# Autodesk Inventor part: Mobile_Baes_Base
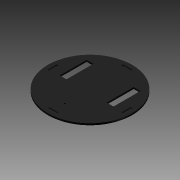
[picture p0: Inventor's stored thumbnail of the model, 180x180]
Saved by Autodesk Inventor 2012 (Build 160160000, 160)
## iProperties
Created: 2014-02
Part Number: Mobile_Baes_Base
Material: Default
Document SubType Name: Modeling
Designer: Aser
Density: 1 g/cm^3
Author: Aser
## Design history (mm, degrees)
sketch "Sketch1"
  geometry: C1 r 250 at (0, 0); 1 further point
  constraints: 1 centre point, 1 coincident
  dimensions: "d0" = 500 diameter of C1
extrude "Extrusion1" new body sketch "Sketch1" distance "d1" = 10; taper "d2" = 0 deg
sketch "Sketch2"
  geometry: L1 (-160, 140)-(-120, 140); L2 (-120, 140)-(-120, -20); L3 (-120, -20)-(-160, -20); L4 (-160, -20)-(-160, 140); L5 (120, 140)-(160, 140); L6 (160, 140)-(160, -20); L7 (160, -20)-(120, -20); L8 (120, -20)-(120, 140); L9 (0, 0)-(250, 0); L10 (0, 0)-(-250, 0); A1 r 250 centre (0, 0) between (250, 0) and (-250, 0) reference
  constraints: 20 end point, 5 equal length, 3 perpendicular, 2 horizontal, 2 point on circle
  dimensions: "d3" = 40 distance of L2.end L3.end; "d4" = 160 distance of L1.end L2.end; "d5" = 40 distance of L6.end L7.end; "d6" = 160 distance of L5.end L6.end; "d8" = 20 distance between parallel lines of L10 L3 (= d9); "d9" = 20 distance between parallel lines of L9 L7; "d10" = 120 distance from line of L9.start L8; "d11" = 120 distance from line of L9.start L2 (= d10)
extrude "Extrusion2" cut sketch "Sketch2" distance "d12" = 10; taper "d13" = 0 deg
sketch "Sketch3"
  geometry: C1 r 250 at (0, 0) reference; C2 r 4 at (0, -150)
  constraints: 1 centre point
  dimensions: "d14" = 8 diameter of C2; "d15" = 150 distance of C1.centre C2.centre
extrude "Extrusion3" cut sketch "Sketch3" distance "d16" = 10; taper "d17" = 0 deg
sketch "Sketch4"
  geometry: L1 (-27.5, 225)-(27.5, 225); L2 (27.5, 225)-(27.5, 215); L3 (27.5, 215)-(-27.5, 215); L4 (-27.5, 215)-(-27.5, 225); L5 (0, 0)-(0, 54.86); L6 (-215, -27.5)-(-225, -27.5); L7 (-215, 27.5)-(-215, -27.5); L8 (-225, -27.5)-(-225, 27.5); L9 (-225, 27.5)-(-215, 27.5); L10 (27.5, -215)-(27.5, -225); L11 (-27.5, -215)-(27.5, -215); L12 (27.5, -225)-(-27.5, -225); L13 (-27.5, -225)-(-27.5, -215); L14 (215, 27.5)-(225, 27.5); L15 (215, -27.5)-(215, 27.5); L16 (225, 27.5)-(225, -27.5); L17 (225, -27.5)-(215, -27.5); C1 r 250 at (0, 0) reference
  constraints: 34 end point, 3 parallel, 1 horizontal, 1 perpendicular, 33 other
  dimensions: "d18" = 55 distance of L2.end L3.end; "d19" = 10 distance of L1.end L2.end; "d20" = 215 distance from line of L3 L5.start; "d21" = 27.5 distance between parallel lines of L5 L4; "d24" = 360 deg dimension on L5.start L3.end (derived)
extrude "Extrusion4" cut sketch "Sketch4" distance "d26" = 5; taper "d27" = 0 deg
body "Solid1"
